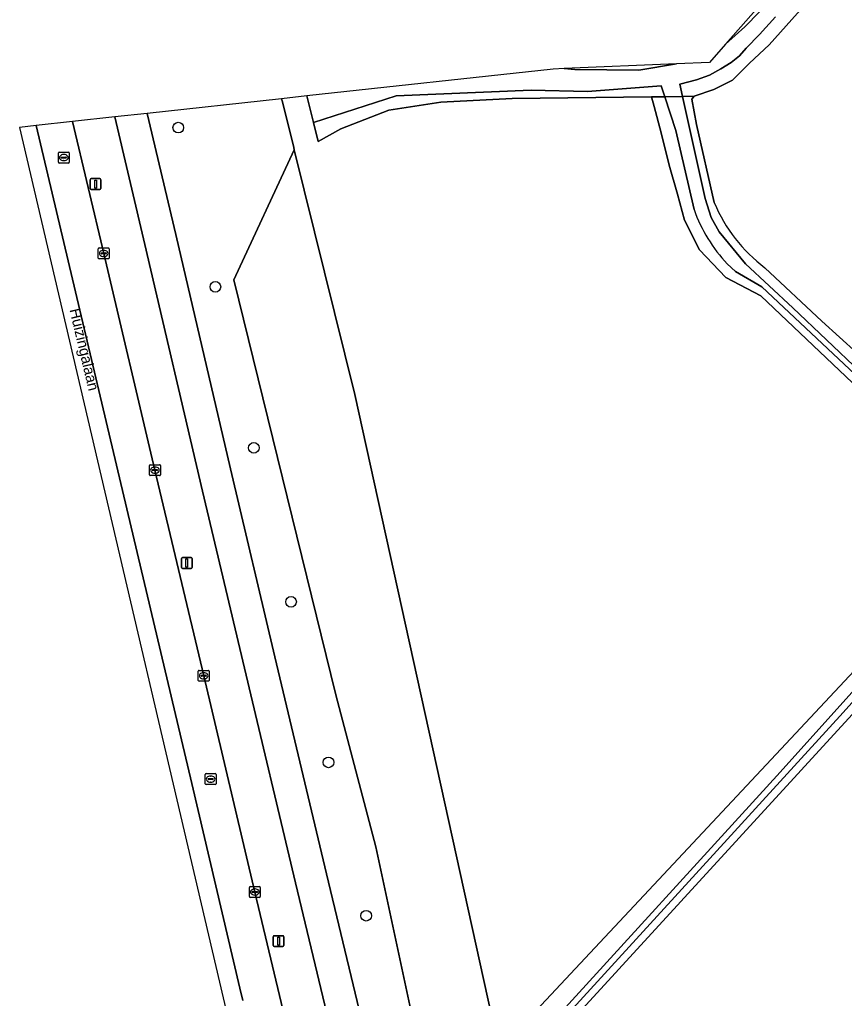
# Model space of a CAD drawing. Extents: x 159626 to 160723, y 388173 to 389416.
# Drawn here: x 159626.3 to 159702.1, y 388321.9 to 388411.9 of the extents above; entities that cross this region are included whole.
import ezdxf

# ---------------------------------------------------------------- set-up
doc = ezdxf.new("R2010")
doc.units = 0
for name, color, linetype in [('IMGEO_Berm_groen', 7, 'Continuous'), ('IMGEO_Boom', 7, 'Continuous'), ('IMGEO_Bouwland', 7, 'Continuous'), ('IMGEO_Fietspad_gesloten', 7, 'Continuous'), ('IMGEO_Grasland_overig', 7, 'Continuous'), ('IMGEO_Groenvoorziening', 7, 'Continuous'), ('IMGEO_Kolk', 7, 'Continuous'), ('IMGEO_Lichtmast', 7, 'Continuous'), ('IMGEO_Loofbos', 7, 'Continuous'), ('IMGEO_Oever', 7, 'Continuous'), ('IMGEO_Openbare_ruimte_label', 7, 'Continuous'), ('IMGEO_OVBaan_gesloten', 7, 'Continuous'), ('IMGEO_Rijbaan_regionaal_gesloten', 7, 'Continuous'), ('IMGEO_Rioolput', 7, 'Continuous'), ('IMGEO_Waterloop', 7, 'Continuous')]:
    doc.layers.add(name, color=color, linetype=linetype)

msp = doc.modelspace()

# ---------------------------------------------------------------- linework, layer by layer
at = {"layer": 'IMGEO_Berm_groen'}
for points in [[(159665.441, 388274.865), (159663.273, 388284.093), (159655.79, 388315.322), (159651.652, 388332.577), (159646.972, 388352.292), (159643.113, 388368.538), (159637.816, 388391.226), (159635.066, 388402.93), (159631.158, 388402.502)], [(159631.158, 388402.502), (159634.032, 388390.393), (159638.738, 388370.484), (159643.217, 388351.589), (159647.917, 388331.722), (159651.959, 388314.77), (159656.659, 388294.911), (159661.358, 388275.039), (159661.616, 388274.008)]]:
    msp.add_lwpolyline(points, dxfattribs=at)
at = {"layer": 'IMGEO_Boom'}
for centre in [(159640.88, 388401.951), (159644.291, 388387.33), (159647.821, 388372.533), (159651.239, 388358.384), (159654.68, 388343.633), (159658.143, 388329.545)]:
    msp.add_circle(centre, 0.489, dxfattribs=at)
at = {"layer": 'IMGEO_Bouwland'}
msp.add_lwpolyline([(159756.626, 388319.581), (159718.63, 388359.302), (159719.472, 388360.074), (159716.531, 388363.091), (159703.473, 388348.782), (159675.986, 388318.774)], dxfattribs=at)
at = {"layer": 'IMGEO_Fietspad_gesloten'}
msp.add_lwpolyline([(159638.028, 388403.254), (159635.066, 388402.93), (159637.816, 388391.226), (159643.113, 388368.538), (159646.972, 388352.292), (159651.652, 388332.577), (159655.79, 388315.322), (159663.273, 388284.093), (159665.441, 388274.865), (159665.942, 388272.81), (159668.868, 388273.517), (159668.467, 388275.203), (159668.457, 388275.2), (159666.059, 388285.291), (159658.451, 388316.958), (159654.5, 388333.379), (159649.758, 388353.315), (159645.676, 388370.594), (159640.646, 388392.14), (159638.028, 388403.254)], dxfattribs=at)
at = {"layer": 'IMGEO_Grasland_overig'}
for points in [[(159776.009, 388404.236), (159776.435, 388405.923), (159757.047, 388412.688), (159742.509, 388417.493), (159728.361, 388422.852), (159712.973, 388429.121), (159711.255, 388429.863), (159710.611, 388428.507), (159709.93, 388427.42), (159708.494, 388425.485), (159707.404, 388423.771), (159705.512, 388421.825), (159703.529, 388419.289), (159700.91, 388415.656), (159697.758, 388412.48), (159695.165, 388409.562), (159693.354, 388407.86), (159691.793, 388406.299), (159690.081, 388405.47), (159688.265, 388404.847), (159688.049, 388404.58), (159688.478, 388402.241), (159690.127, 388395.066)], [(159694.784, 388389.084), (159700, 388384.168), (159717.863, 388367.996), (159752.373, 388405.535), (159754.207, 388405.962), (159754.168, 388404.331), (159759.918, 388409.633), (159776.009, 388404.236)]]:
    msp.add_lwpolyline(points, dxfattribs=at)
msp.add_arc((159703.407, 388400.601), 14.388, 202.6257, 233.17597, dxfattribs=at)
at = {"layer": 'IMGEO_Groenvoorziening'}
for points in [[(159650.369, 388404.604), (159638.028, 388403.254), (159640.646, 388392.14), (159645.676, 388370.594), (159649.758, 388353.315), (159654.5, 388333.379), (159658.451, 388316.958), (159666.059, 388285.291), (159668.457, 388275.2), (159668.467, 388275.203), (159671.009, 388275.813), (159675.748, 388255.812), (159681.747, 388230.498), (159687.118, 388207.948)], [(159690.534, 388205.123), (159691.701, 388205.347), (159675.649, 388277.453), (159671.066, 388279.691), (159659.023, 388335.866), (159655.37, 388349.825), (159645.988, 388387.96), (159651.536, 388399.899), (159651.482, 388400.116), (159650.441, 388404.315), (159650.369, 388404.604)]]:
    msp.add_lwpolyline(points, dxfattribs=at)
msp.add_lwpolyline([(159657.112, 388377.421), (159651.536, 388399.899), (159645.988, 388387.96), (159655.37, 388349.825), (159659.023, 388335.866), (159671.066, 388279.691), (159675.649, 388277.453), (159691.701, 388205.347), (159696.758, 388206.32), (159696.998, 388206.367), (159696.727, 388207.495), (159670.036, 388318.729)], close=True, dxfattribs=at)
at = {"layer": 'IMGEO_Kolk'}
for p, q in [((159633.531, 388389.967), (159633.531, 388390.819)), ((159633.606, 388390.893), (159634.458, 388390.893)), ((159633.833, 388390.436), (159634.231, 388390.436)), ((159634.019, 388390.673), (159634.044, 388390.673)), ((159634.532, 388390.819), (159634.532, 388389.967)), ((159634.458, 388389.893), (159633.606, 388389.893)), ((159633.79, 388390.387), (159633.79, 388390.399)), ((159634.228, 388390.35), (159633.83, 388390.35)), ((159634.042, 388390.113), (159634.017, 388390.113)), ((159634.274, 388390.399), (159634.274, 388390.387)), ((159638.237, 388370.058), (159638.237, 388370.91)), ((159638.312, 388370.984), (159639.164, 388370.984)), ((159638.725, 388370.764), (159638.75, 388370.764)), ((159639.238, 388370.91), (159639.238, 388370.058)), ((159639.164, 388369.984), (159638.312, 388369.984)), ((159638.496, 388370.478), (159638.496, 388370.49)), ((159638.934, 388370.441), (159638.536, 388370.441)), ((159638.539, 388370.527), (159638.937, 388370.527)), ((159638.748, 388370.204), (159638.723, 388370.204)), ((159638.98, 388370.49), (159638.98, 388370.478)), ((159642.716, 388351.163), (159642.716, 388352.015)), ((159642.791, 388352.089), (159643.643, 388352.089)), ((159643.204, 388351.869), (159643.229, 388351.869)), ((159643.717, 388352.015), (159643.717, 388351.163)), ((159643.643, 388351.089), (159642.791, 388351.089)), ((159642.975, 388351.583), (159642.975, 388351.595)), ((159643.413, 388351.546), (159643.015, 388351.546)), ((159643.018, 388351.632), (159643.416, 388351.632)), ((159643.227, 388351.309), (159643.202, 388351.309)), ((159643.459, 388351.595), (159643.459, 388351.583)), ((159647.416, 388331.296), (159647.416, 388332.148)), ((159647.491, 388332.222), (159648.343, 388332.222)), ((159647.904, 388332.002), (159647.929, 388332.002)), ((159648.417, 388332.148), (159648.417, 388331.296)), ((159648.343, 388331.222), (159647.491, 388331.222)), ((159647.675, 388331.716), (159647.675, 388331.728)), ((159648.113, 388331.679), (159647.715, 388331.679)), ((159647.718, 388331.765), (159648.116, 388331.765)), ((159647.927, 388331.442), (159647.902, 388331.442)), ((159648.159, 388331.728), (159648.159, 388331.716))]:
    msp.add_line(p, q, dxfattribs=at)
for points in [[(159633.531, 388389.967), (159633.531, 388390.819)], [(159633.606, 388390.893), (159634.458, 388390.893)], [(159634.532, 388390.819), (159634.532, 388389.967)], [(159634.458, 388389.893), (159633.606, 388389.893)], [(159638.237, 388370.058), (159638.237, 388370.91)], [(159638.312, 388370.984), (159639.164, 388370.984)], [(159639.238, 388370.91), (159639.238, 388370.058)], [(159639.164, 388369.984), (159638.312, 388369.984)], [(159642.716, 388351.163), (159642.716, 388352.015)], [(159642.791, 388352.089), (159643.643, 388352.089)], [(159643.717, 388352.015), (159643.717, 388351.163)], [(159643.643, 388351.089), (159642.791, 388351.089)], [(159647.416, 388331.296), (159647.416, 388332.148)], [(159647.491, 388332.222), (159648.343, 388332.222)], [(159648.417, 388332.148), (159648.417, 388331.296)], [(159648.343, 388331.222), (159647.491, 388331.222)]]:
    msp.add_lwpolyline(points, dxfattribs=at)
for centre, radius, start, end in [((159633.608, 388390.817), 0.0765, 91.55205, 178.44795), ((159633.608, 388390.817), 0.0765, 91.55205, 178.44795), ((159633.83, 388390.396), 0.0403, 85.87752, 175.75265), ((159634.235, 388390.398), 0.0386, 1.73085, 96.63898), ((159634.456, 388390.817), 0.0765, 1.55205, 88.44795), ((159634.456, 388390.817), 0.0765, 1.55205, 88.44795), ((159633.608, 388389.969), 0.0765, 181.55205, 268.44795), ((159633.608, 388389.969), 0.0765, 181.55205, 268.44795), ((159633.827, 388390.386), 0.0366, 178.93798, 274.71019), ((159634.231, 388390.393), 0.043, 264.86636, 352.45326), ((159634.456, 388389.969), 0.0765, 271.55205, 358.44795), ((159634.456, 388389.969), 0.0765, 271.55205, 358.44795), ((159638.314, 388370.908), 0.0765, 91.55205, 178.44795), ((159638.314, 388370.908), 0.0765, 91.55205, 178.44795), ((159639.162, 388370.908), 0.0765, 1.55205, 88.44795), ((159639.162, 388370.908), 0.0765, 1.55205, 88.44795), ((159638.314, 388370.06), 0.0765, 181.55205, 268.44795), ((159638.314, 388370.06), 0.0765, 181.55205, 268.44795), ((159638.536, 388370.487), 0.0403, 85.87752, 175.75265), ((159638.533, 388370.477), 0.0366, 178.93798, 274.71019), ((159638.937, 388370.484), 0.043, 264.86636, 352.45326), ((159638.941, 388370.489), 0.0386, 1.73085, 96.63898), ((159639.162, 388370.06), 0.0765, 271.55205, 358.44795), ((159639.162, 388370.06), 0.0765, 271.55205, 358.44795), ((159642.793, 388352.013), 0.0765, 91.55205, 178.44795), ((159642.793, 388352.013), 0.0765, 91.55205, 178.44795), ((159643.641, 388352.013), 0.0765, 1.55205, 88.44795), ((159643.641, 388352.013), 0.0765, 1.55205, 88.44795), ((159642.793, 388351.165), 0.0765, 181.55205, 268.44795), ((159642.793, 388351.165), 0.0765, 181.55205, 268.44795), ((159643.015, 388351.592), 0.0403, 85.87752, 175.75265), ((159643.012, 388351.582), 0.0366, 178.93798, 274.71019), ((159643.416, 388351.589), 0.043, 264.86636, 352.45326), ((159643.42, 388351.594), 0.0386, 1.73085, 96.63898), ((159643.641, 388351.165), 0.0765, 271.55205, 358.44795), ((159643.641, 388351.165), 0.0765, 271.55205, 358.44795), ((159647.493, 388332.146), 0.0765, 91.55205, 178.44795), ((159647.493, 388332.146), 0.0765, 91.55205, 178.44795), ((159648.341, 388332.146), 0.0765, 1.55205, 88.44795), ((159648.341, 388332.146), 0.0765, 1.55205, 88.44795), ((159647.493, 388331.298), 0.0765, 181.55205, 268.44795), ((159647.493, 388331.298), 0.0765, 181.55205, 268.44795), ((159647.715, 388331.725), 0.0403, 85.87752, 175.75265), ((159647.712, 388331.715), 0.0366, 178.93798, 274.71019), ((159648.116, 388331.722), 0.043, 264.86636, 352.45326), ((159648.12, 388331.727), 0.0386, 1.73085, 96.63898), ((159648.341, 388331.298), 0.0765, 271.55205, 358.44795), ((159648.341, 388331.298), 0.0765, 271.55205, 358.44795)]:
    msp.add_arc(centre, radius, start, end, dxfattribs=at)
for centre, major_axis, ratio, start_param, end_param in [((159634.018, 388390.393), (-0.387, 0.002), 0.722429, 4.712389, 7.853982), ((159634.043, 388390.393), (-0.39, 0.002), 0.717154, 1.570796, 4.712389), ((159638.724, 388370.484), (-0.387, 0.002), 0.722429, 4.712389, 7.853982), ((159638.749, 388370.484), (-0.39, 0.002), 0.717154, 1.570796, 4.712389), ((159643.203, 388351.589), (-0.387, 0.002), 0.722429, 4.712389, 7.853982), ((159643.228, 388351.589), (-0.39, 0.002), 0.717154, 1.570796, 4.712389), ((159647.903, 388331.722), (-0.387, 0.002), 0.722429, 4.712389, 7.853982), ((159647.928, 388331.722), (-0.39, 0.002), 0.717154, 1.570796, 4.712389)]:
    msp.add_ellipse(centre, major_axis=major_axis, ratio=ratio, start_param=start_param, end_param=end_param, dxfattribs=at)
at = {"layer": 'IMGEO_Lichtmast'}
for p, q in [((159632.784, 388396.365), (159632.784, 388397.165)), ((159632.784, 388397.165), (159632.784, 388396.365)), ((159632.884, 388397.265), (159633.674, 388397.265)), ((159633.674, 388397.265), (159632.884, 388397.265)), ((159633.774, 388397.165), (159633.774, 388396.365)), ((159633.774, 388396.365), (159633.774, 388397.165)), ((159633.674, 388396.265), (159632.884, 388396.265)), ((159632.884, 388396.265), (159633.674, 388396.265)), ((159641.168, 388361.55), (159641.168, 388362.35)), ((159641.168, 388362.35), (159641.168, 388361.55)), ((159641.268, 388362.45), (159642.058, 388362.45)), ((159642.058, 388362.45), (159641.268, 388362.45)), ((159642.158, 388362.35), (159642.158, 388361.55)), ((159642.158, 388361.55), (159642.158, 388362.35)), ((159642.058, 388361.45), (159641.268, 388361.45)), ((159641.268, 388361.45), (159642.058, 388361.45)), ((159649.598, 388326.811), (159649.598, 388327.611)), ((159649.598, 388327.611), (159649.598, 388326.811)), ((159649.698, 388327.711), (159650.488, 388327.711)), ((159650.488, 388327.711), (159649.698, 388327.711)), ((159650.588, 388327.611), (159650.588, 388326.811)), ((159650.588, 388326.811), (159650.588, 388327.611)), ((159650.488, 388326.711), (159649.698, 388326.711)), ((159649.698, 388326.711), (159650.488, 388326.711))]:
    msp.add_line(p, q, dxfattribs=at)
for points in [[(159633.204, 388397.14), (159633.354, 388397.14), (159633.354, 388396.39), (159633.204, 388396.39), (159633.204, 388397.14)], [(159641.588, 388362.325), (159641.738, 388362.325), (159641.738, 388361.575), (159641.588, 388361.575), (159641.588, 388362.325)], [(159650.018, 388327.586), (159650.168, 388327.586), (159650.168, 388326.836), (159650.018, 388326.836), (159650.018, 388327.586)]]:
    msp.add_lwpolyline(points, dxfattribs=at)
for centre, start, end in [((159632.884, 388397.165), 90, 180), ((159632.884, 388397.165), 90, 180), ((159633.674, 388397.165), 0, 90), ((159633.674, 388397.165), 360, 90), ((159632.884, 388396.365), 180, 270), ((159632.884, 388396.365), 180, 270), ((159633.674, 388396.365), 270, 0), ((159633.674, 388396.365), 270, 0), ((159641.268, 388362.35), 90, 180), ((159641.268, 388362.35), 90, 180), ((159642.058, 388362.35), 0, 90), ((159642.058, 388362.35), 360, 90), ((159641.268, 388361.55), 180, 270), ((159641.268, 388361.55), 180, 270), ((159642.058, 388361.55), 270, 0), ((159642.058, 388361.55), 270, 0), ((159649.698, 388327.611), 90, 180), ((159649.698, 388327.611), 90, 180), ((159650.488, 388327.611), 0, 90), ((159650.488, 388327.611), 360, 90), ((159649.698, 388326.811), 180, 270), ((159649.698, 388326.811), 180, 270), ((159650.488, 388326.811), 270, 0), ((159650.488, 388326.811), 270, 0)]:
    msp.add_arc(centre, 0.1, start, end, dxfattribs=at)
at = {"layer": 'IMGEO_Loofbos'}
msp.add_lwpolyline([(159672.883, 388319.887), (159716.015, 388365.984), (159694.417, 388386.495), (159691.178, 388388.183), (159688.77, 388390.724), (159687.381, 388393.463), (159686.746, 388395.844), (159685.992, 388398.503), (159685.231, 388401.459), (159684.603, 388403.9), (159684.365, 388404.774), (159671.546, 388404.615), (159664.997, 388404.297), (159660.235, 388403.543), (159655.829, 388401.837), (159653.724, 388400.689), (159653.302, 388402.41), (159652.702, 388404.859), (159650.369, 388404.604), (159650.441, 388404.315), (159651.482, 388400.116), (159651.536, 388399.899), (159657.112, 388377.421), (159670.036, 388318.729)], dxfattribs=at)
at = {"layer": 'IMGEO_Oever'}
for points in [[(159703.987, 388424.177), (159691.169, 388409.635), (159692.93, 388411.223), (159695.599, 388413.974), (159702.581, 388422.229)], [(159686.669, 388407.818), (159676.33, 388407.377), (159677.324, 388407.28), (159683.197, 388407.239)], [(159684.365, 388404.774), (159685.578, 388404.796), (159685.252, 388405.803), (159678.478, 388405.277), (159673.305, 388405.379), (159660.897, 388404.878), (159653.302, 388402.41), (159653.724, 388400.689), (159655.829, 388401.837), (159660.235, 388403.543), (159664.997, 388404.297), (159671.546, 388404.615)]]:
    msp.add_lwpolyline(points, close=True, dxfattribs=at)
for points in [[(159695.757, 388412.118), (159694.29, 388410.497), (159693.046, 388409.251), (159692.452, 388408.536), (159691.666, 388407.942), (159690.721, 388407.365), (159689.687, 388406.768), (159688.485, 388406.357), (159686.971, 388405.936), (159687.217, 388404.827), (159688.265, 388404.847), (159690.081, 388405.47), (159691.793, 388406.299), (159693.354, 388407.86), (159695.165, 388409.562), (159697.758, 388412.48)], [(159675.986, 388318.774), (159703.473, 388348.782), (159716.531, 388363.091), (159726.882, 388373.344), (159754.168, 388404.331), (159754.207, 388405.962), (159752.373, 388405.535), (159717.863, 388367.996), (159700, 388384.168), (159694.784, 388389.084)], [(159690.127, 388395.066), (159688.478, 388402.241), (159688.049, 388404.58), (159688.265, 388404.847), (159687.217, 388404.827), (159689.301, 388395.429), (159689.835, 388393.704), (159690.574, 388392.39), (159692.997, 388389.433), (159697.35, 388385.409), (159706.631, 388376.579), (159717.761, 388366.723), (159752.863, 388404.977), (159753.536, 388404.505), (159721.585, 388369.716), (159718.043, 388366.04)], [(159688.271, 388394.415), (159686.587, 388401.678), (159685.578, 388404.796), (159684.365, 388404.774), (159684.603, 388403.9), (159685.231, 388401.459), (159685.992, 388398.503), (159686.746, 388395.844), (159687.381, 388393.463), (159688.77, 388390.724), (159691.178, 388388.183), (159694.417, 388386.495), (159716.015, 388365.984), (159672.883, 388319.887)], [(159718.043, 388366.04), (159701.667, 388347.868), (159675.199, 388318.894), (159703.967, 388276.574), (159724.83, 388245.855), (159736.657, 388228.155), (159736.854, 388227.596), (159736.432, 388227.435), (159736.082, 388227.826), (159674.542, 388318.997), (159695.877, 388342.406), (159717.144, 388366.045), (159694.506, 388387.325), (159692.075, 388388.719), (159691.323, 388389.433)]]:
    msp.add_lwpolyline(points, dxfattribs=at)
for centre, radius, start, end in [((159703.407, 388400.601), 14.388, 202.6257, 233.17597), ((159701.685, 388399.207), 14.245, 199.65777, 223.32595)]:
    msp.add_arc(centre, radius, start, end, dxfattribs=at)
at = {"layer": 'IMGEO_OVBaan_gesloten'}
for points in [[(159627.828, 388402.138), (159626.3, 388401.971), (159649.589, 388302.356)], [(159646.825, 388321.77), (159646.543, 388322.887), (159642.127, 388341.705), (159633.305, 388378.957), (159627.828, 388402.138)]]:
    msp.add_lwpolyline(points, dxfattribs=at)
at = {"layer": 'IMGEO_Rijbaan_regionaal_gesloten'}
msp.add_lwpolyline([(159661.114, 388253.057), (159665.136, 388235.853), (159670.373, 388237.115), (159669.468, 388240.849), (159668.472, 388245.049), (159664.776, 388260.591), (159663.16, 388267.338), (159662.382, 388270.647), (159661.616, 388274.008), (159661.358, 388275.039), (159656.659, 388294.911), (159651.959, 388314.77), (159647.917, 388331.722), (159643.217, 388351.589), (159638.738, 388370.484), (159634.032, 388390.393), (159631.158, 388402.502), (159627.828, 388402.138), (159633.305, 388378.957), (159642.127, 388341.705), (159646.543, 388322.887), (159646.825, 388321.77)], dxfattribs=at)
at = {"layer": 'IMGEO_Rioolput'}
for p, q in [((159629.864, 388398.773), (159629.864, 388399.625)), ((159629.939, 388399.699), (159630.791, 388399.699)), ((159630.352, 388399.479), (159630.377, 388399.479)), ((159630.865, 388399.625), (159630.865, 388398.773)), ((159630.791, 388398.699), (159629.939, 388398.699)), ((159630.123, 388399.193), (159630.123, 388399.205)), ((159630.561, 388399.156), (159630.163, 388399.156)), ((159630.166, 388399.242), (159630.564, 388399.242)), ((159630.375, 388398.919), (159630.35, 388398.919)), ((159630.607, 388399.205), (159630.607, 388399.193)), ((159643.353, 388341.672), (159643.353, 388342.524)), ((159643.428, 388342.598), (159644.28, 388342.598)), ((159643.612, 388342.092), (159643.612, 388342.104)), ((159644.05, 388342.055), (159643.652, 388342.055)), ((159643.655, 388342.141), (159644.053, 388342.141)), ((159643.841, 388342.378), (159643.866, 388342.378)), ((159644.096, 388342.104), (159644.096, 388342.092)), ((159644.354, 388342.524), (159644.354, 388341.672)), ((159644.28, 388341.598), (159643.428, 388341.598)), ((159643.864, 388341.818), (159643.839, 388341.818))]:
    msp.add_line(p, q, dxfattribs=at)
for points in [[(159629.864, 388398.773), (159629.864, 388399.625)], [(159629.939, 388399.699), (159630.791, 388399.699)], [(159630.865, 388399.625), (159630.865, 388398.773)], [(159630.791, 388398.699), (159629.939, 388398.699)], [(159643.353, 388341.672), (159643.353, 388342.524)], [(159643.428, 388342.598), (159644.28, 388342.598)], [(159644.354, 388342.524), (159644.354, 388341.672)], [(159644.28, 388341.598), (159643.428, 388341.598)]]:
    msp.add_lwpolyline(points, dxfattribs=at)
for centre, radius, start, end in [((159629.941, 388399.623), 0.0765, 91.55205, 178.44795), ((159629.941, 388399.623), 0.0765, 91.55205, 178.44795), ((159630.789, 388399.623), 0.0765, 1.55205, 88.44795), ((159630.789, 388399.623), 0.0765, 1.55205, 88.44795), ((159629.941, 388398.775), 0.0765, 181.55205, 268.44795), ((159629.941, 388398.775), 0.0765, 181.55205, 268.44795), ((159630.163, 388399.202), 0.0403, 85.87752, 175.75265), ((159630.16, 388399.192), 0.0366, 178.93798, 274.71019), ((159630.564, 388399.199), 0.043, 264.86636, 352.45326), ((159630.568, 388399.204), 0.0386, 1.73085, 96.63898), ((159630.789, 388398.775), 0.0765, 271.55205, 358.44795), ((159630.789, 388398.775), 0.0765, 271.55205, 358.44795), ((159643.43, 388342.522), 0.0765, 91.55205, 178.44795), ((159643.43, 388342.522), 0.0765, 91.55205, 178.44795), ((159643.652, 388342.101), 0.0403, 85.87752, 175.75265), ((159643.649, 388342.091), 0.0366, 178.93798, 274.71019), ((159644.053, 388342.098), 0.043, 264.86636, 352.45326), ((159644.057, 388342.103), 0.0386, 1.73085, 96.63898), ((159644.278, 388342.522), 0.0765, 1.55205, 88.44795), ((159644.278, 388342.522), 0.0765, 1.55205, 88.44795), ((159643.43, 388341.674), 0.0765, 181.55205, 268.44795), ((159643.43, 388341.674), 0.0765, 181.55205, 268.44795), ((159644.278, 388341.674), 0.0765, 271.55205, 358.44795), ((159644.278, 388341.674), 0.0765, 271.55205, 358.44795)]:
    msp.add_arc(centre, radius, start, end, dxfattribs=at)
for centre, major_axis, ratio, start_param, end_param in [((159630.351, 388399.199), (-0.387, 0.002), 0.722429, 4.712389, 7.853982), ((159630.376, 388399.199), (-0.39, 0.002), 0.717154, 1.570796, 4.712389), ((159643.84, 388342.098), (-0.387, 0.002), 0.722429, 4.712389, 7.853982), ((159643.865, 388342.098), (-0.39, 0.002), 0.717154, 1.570796, 4.712389)]:
    msp.add_ellipse(centre, major_axis=major_axis, ratio=ratio, start_param=start_param, end_param=end_param, dxfattribs=at)
at = {"layer": 'IMGEO_Waterloop'}
for points in [[(159695.599, 388413.974), (159692.93, 388411.223), (159691.169, 388409.635), (159689.681, 388407.947), (159686.669, 388407.818), (159683.197, 388407.239), (159677.324, 388407.28), (159676.33, 388407.377), (159675.331, 388407.334), (159652.702, 388404.859), (159653.302, 388402.41), (159660.897, 388404.878), (159673.305, 388405.379), (159678.478, 388405.277), (159685.252, 388405.803), (159685.578, 388404.796), (159687.217, 388404.827), (159686.971, 388405.936), (159688.485, 388406.357), (159689.687, 388406.768), (159690.721, 388407.365), (159691.666, 388407.942), (159692.452, 388408.536), (159693.046, 388409.251), (159694.29, 388410.497), (159695.757, 388412.118)], [(159691.323, 388389.433), (159692.075, 388388.719), (159694.506, 388387.325), (159717.144, 388366.045), (159695.877, 388342.406), (159674.542, 388318.997), (159736.082, 388227.826), (159736.432, 388227.435), (159736.854, 388227.596), (159736.657, 388228.155), (159724.83, 388245.855), (159703.967, 388276.574), (159675.199, 388318.894), (159701.667, 388347.868), (159718.043, 388366.04), (159717.761, 388366.723), (159706.631, 388376.579), (159697.35, 388385.409), (159692.997, 388389.433), (159690.574, 388392.39), (159689.835, 388393.704), (159689.301, 388395.429), (159687.217, 388404.827)], [(159687.217, 388404.827), (159685.578, 388404.796), (159686.587, 388401.678), (159688.271, 388394.415)]]:
    msp.add_lwpolyline(points, dxfattribs=at)
msp.add_arc((159701.685, 388399.207), 14.245, 199.65777, 223.32595, dxfattribs=at)

# ---------------------------------------------------------------- texts
at = {"layer": 'IMGEO_Openbare_ruimte_label'}
msp.add_text('Huizingalaan', height=1, rotation=283.29958, dxfattribs=at).set_placement((159630.88, 388385.22))

doc.saveas('drawing.dxf')
